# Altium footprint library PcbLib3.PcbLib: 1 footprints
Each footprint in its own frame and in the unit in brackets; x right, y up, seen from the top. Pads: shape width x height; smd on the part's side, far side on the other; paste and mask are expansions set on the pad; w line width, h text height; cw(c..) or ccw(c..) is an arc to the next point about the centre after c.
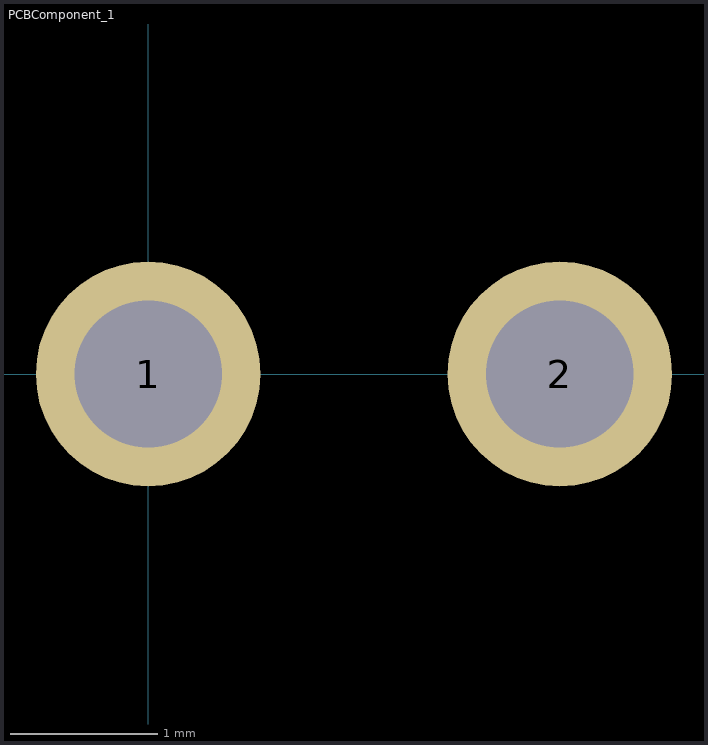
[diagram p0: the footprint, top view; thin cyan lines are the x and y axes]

## PCBComponent_1 [mil]
pads (2):
  round 60 hole 39.37: 1(0,0) 2(110,0)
